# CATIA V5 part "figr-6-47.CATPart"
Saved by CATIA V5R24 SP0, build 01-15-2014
Part number: Part1
Bounding box of the stored display mesh (mm): x 0 to 100, y -60 to 60, z -50 to 50
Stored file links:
  D:\KAVITA\CATIA V5-6R2014 Project_ Kavita\CATIA V5-6R2014_partfiles\Partfiles\c06_catia_v5-6r2014_prt\figr-6-47.CATPart
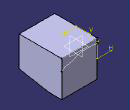
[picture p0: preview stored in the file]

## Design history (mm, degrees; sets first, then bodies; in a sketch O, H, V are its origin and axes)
Body1 (main body)
  Sketch1 on yz-plane, origin (0, 0, 0), H (0, 1, 0), V (0, 0, 1)
    line L1 (60, 50) -> (60, -50)
    line L2 (60, -50) -> (25, -50)
    line L3 (-60, -35) -> (-60, 50)
    line L4 (-60, 50) -> (60, 50)
    point P2 (60, -50)
    point P3 (-60, -50)
    line L5 (25, -50) -> (-60, -35)
    point P5 (25, -50)
    point P6 (-60, -35)
    length L1 = 100
    distance P2 P3 = 120
    distance P5 P3 = 85
    distance P6 P3 = 15
    vertical: L1 V, L3 V
    horizontal: L2 H, L4 H
    equidistance: L1 L3 O, L2 L4 O
    coincidence: L2 P3, L3 P3
  Pad1: profile Sketch1, direction (1, 0, 0), length 100
  Sketch2 on face of Pad1 from Sketch1.L1, origin (0, 60, 0), H (-1, 0, 0), V (0, 0, 1)
    spline S1 through (-100, 18.28) (-85.0256, 26.4663) (-71, 29) (-63.0256, 32.4663) (-31, 39) (-16, 39) (0, 37.4663)
    reference projected line E1 (-100, -50) -> (-100, 50) from edge [face of Pad1 from Sketch1.L1 | end face of Pad1]
    reference projected line E2 (0, -50) -> (0, 50) from edge [start face of Pad1 | face of Pad1 from Sketch1.L1]
    point P1 (0, 37.4663)
    point P2 (-100, 18.28)
    coincidence: P1 V, P2 E1, P1 E2
  Sketch3 on face of Pad1 from Sketch1.L4, origin (0, 0, 50), H (1, 0, 0), V (0, 1, 0)
    projected line E1 (0, 60) -> (100, 60) from Sketch2.S1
